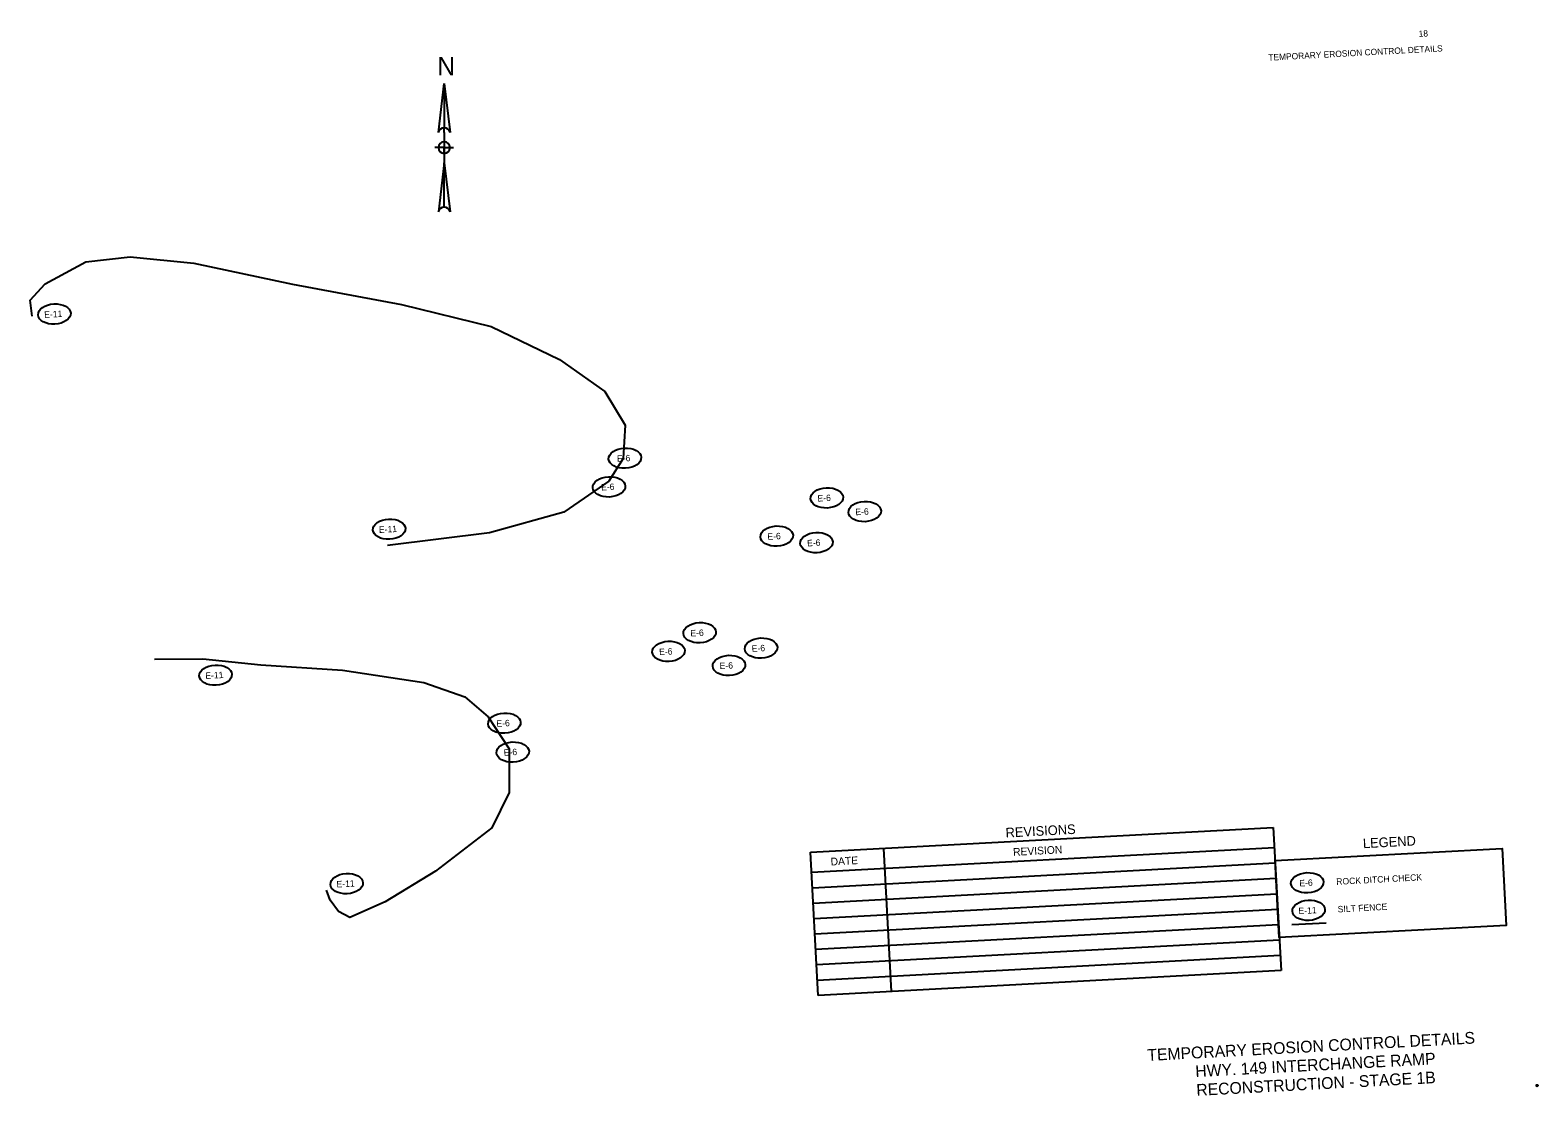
# Model space of a CAD drawing. Extents: x 251493 to 254667, y 216764 to 225410.
# Drawn here: x 251612 to 254429, y 221201 to 223192 of the extents above; entities that cross this region are included whole.
import ezdxf

# ---------------------------------------------------------------- set-up
doc = ezdxf.new("R2010")
doc.units = 0
for name, color, linetype in [('24X36', 7, 'Continuous'), ('Level 1', 7, 'Continuous'), ('Level 2', 7, 'Continuous'), ('Level 30', 7, 'Continuous')]:
    doc.layers.add(name, color=color, linetype=linetype)

msp = doc.modelspace()

# ---------------------------------------------------------------- linework, layer by layer
at = {"layer": '24X36'}
msp.add_line((253969.6, 221520.8), (254033.6, 221524.3), dxfattribs=at)
for points in [[(251615.8, 222657.8), (251611.8, 222687.5), (251640.1, 222717.7), (251715.6, 222758.8), (251798.9, 222768.1), (251917.9, 222756.5), (252101.8, 222717.3), (252306, 222679.2), (252473.2, 222638), (252600.9, 222576.6), (252685.5, 222516.6), (252723.5, 222454), (252719.7, 222391.6), (252693.2, 222349.5), (252609, 222291.2), (252470, 222252.7), (252279.8, 222229.3)], [(251843.9, 222017), (251934.8, 222017.1), (252043, 222006.1), (252195.4, 221996.3), (252347.4, 221973.4), (252424.2, 221946.4), (252468, 221909.3), (252507.1, 221849.2), (252506.7, 221767.8), (252474.4, 221701.5), (252369.3, 221620.5), (252275.4, 221563.5), (252209.4, 221534.2), (252187.9, 221545.6), (252172.4, 221566.3), (252165.4, 221585.1)]]:
    msp.add_lwpolyline(points, dxfattribs=at)
for centre in [(251657.2, 222661.5), (252723.2, 222392.2), (252693.5, 222338.6), (252282.7, 222259.6), (251958.3, 221986.9), (252498, 221897.2), (252513.7, 221843.1), (252203.4, 221597.4)]:
    msp.add_ellipse(centre, major_axis=(30.4, 1.6), ratio=0.622507, dxfattribs=at)
at = {"layer": 'Level 1'}
for p, q in [((252374.6, 223000.8), (252385.5, 223092.2)), ((252385.5, 223092.2), (252396.4, 223000.8)), ((252385.5, 223092.2), (252385.5, 223009.4)), ((252385.5, 223000.8), (252385.5, 223009.4)), ((252385.5, 223000.8), (252385.5, 222983.3)), ((252374.2, 222972.4), (252368.1, 222972.4)), ((252385.5, 222972.4), (252375, 222972.4)), ((252385.5, 222983.3), (252385.5, 222972.4)), ((252385.5, 222972.4), (252385.5, 222961.6)), ((252385.5, 222972.4), (252396.4, 222972.4)), ((252385.5, 222961.6), (252385.5, 222972.4)), ((252396.4, 222972.4), (252402.9, 222972.4)), ((252396.4, 222972.4), (252396.4, 222972.4)), ((252385.5, 222944.1), (252374.6, 222852.7)), ((252385.5, 222961.6), (252385.5, 222944.1)), ((252385.5, 222861.4), (252385.5, 222944.1)), ((252385.5, 222944.1), (252396.4, 222852.7)), ((253069.9, 221655.9), (253934.9, 221702.3)), ((253934.9, 221702.3), (253949.3, 221434.8)), ((253084.3, 221388.4), (253069.9, 221655.9)), ((253071.9, 221618.5), (253936.9, 221664.8)), ((253206.3, 221663.2), (253220.6, 221395.7)), ((253073.5, 221589.7), (253938.5, 221636.1)), ((253075, 221561), (253940, 221607.3)), ((253076.6, 221532.2), (253941.6, 221578.6)), ((253078.1, 221503.5), (253943.1, 221549.8)), ((253079.6, 221474.7), (253944.7, 221521.1)), ((253081.2, 221446), (253946.2, 221492.3)), ((253082.7, 221417.2), (253947.7, 221463.5)), ((253949.3, 221434.8), (253084.3, 221388.4)), ((253949.3, 221434.8), (253949.3, 221434.8))]:
    msp.add_line(p, q, dxfattribs=at)
msp.add_lwpolyline([(253938.3, 221640.4), (254362.4, 221663.1), (254370.1, 221519.3), (253946, 221496.6)], close=True, dxfattribs=at)
for points in [[(254427.2, 221221), (254425.9, 221220.9), (254425.9, 221220.7), (254426.4, 221220.8), (254426.5, 221219.3), (254426.7, 221219.3), (254426.7, 221220.8), (254427.2, 221220.8), (254427.2, 221221)], [(254427.7, 221220.7), (254427.7, 221220.7), (254428.3, 221219.3), (254428.4, 221219.4), (254428.9, 221220.8), (254428.9, 221220.8), (254429, 221219.4), (254429.2, 221219.4), (254429.1, 221221.1), (254428.8, 221221.1), (254428.3, 221219.6), (254427.7, 221221), (254427.4, 221221), (254427.5, 221219.3), (254427.7, 221219.3), (254427.7, 221220.7)]]:
    msp.add_lwpolyline(points, dxfattribs=at)
for centre, radius, start, end in [((252385.5, 222998.3), 11.2, 90, 167.3196), ((252385.5, 222998.3), 11.2, 12.6804, 90), ((252385.5, 222972.4), 10.9, 90, 180), ((252385.5, 222972.4), 10.9, 180, 270), ((252385.5, 222972.4), 10.9, 0, 90), ((252385.5, 222972.4), 10.9, 270, 0), ((252385.5, 222850.2), 11.2, 90, 167.3196), ((252385.5, 222850.2), 11.2, 12.6804, 90)]:
    msp.add_arc(centre, radius, start, end, dxfattribs=at)
at = {"layer": 'Level 30'}
for centre in [(253100.6, 222318), (253171.4, 222292.5), (253007, 222246.6), (253081.2, 222234.5), (252863, 222066.1), (252804.7, 222031.3), (252977.7, 222037.4), (252917.7, 222005), (253998.3, 221599), (254001, 221547.5)]:
    msp.add_ellipse(centre, major_axis=(30.4, 1.6), ratio=0.622507, dxfattribs=at)

# ---------------------------------------------------------------- texts
at = {"layer": '24X36'}
for s, p in [('E-11', (251638.4, 222654.3)), ('E-6', (252708.7, 222385.3)), ('E-6', (252679, 222331.7)), ('E-11', (252263.9, 222252.5)), ('E-11', (251939.5, 221979.7)), ('E-6', (252483.4, 221890.3)), ('E-6', (252497.1, 221836.3)), ('E-11', (252184.6, 221590.2))]:
    msp.add_text(s, height=12, rotation=3.0666, dxfattribs=at).set_placement(p)
at = {"layer": 'Level 1'}
for s, height, p in [('18', 11.72, (254206.8, 223179.2)), ('TEMPORARY EROSION CONTROL DETAILS', 11.7, (253926, 223134.8)), ('DATE', 14.4, (253108, 221631.2)), ('REVISION', 14.4, (253448.9, 221649.2))]:
    msp.add_text(s, height=height, rotation=3.0666, dxfattribs=at).set_placement(p)
msp.add_text('N', height=34.2, dxfattribs=at).set_placement((252372.9, 223107.3))
at = {"layer": 'Level 2'}
for s, p in [('TEMPORARY EROSION CONTROL DETAILS', (253700.1, 221266)), ('HWY. 149 INTERCHANGE RAMP', (253789.7, 221235.8)), ('RECONSTRUCTION - STAGE 1B', (253791.6, 221200.8))]:
    msp.add_text(s, height=22, rotation=3.0666, dxfattribs=at).set_placement(p)
at = {"layer": 'Level 30'}
for s, height, p in [('E-6', 12, (253083.4, 222311)), ('E-6', 12, (253154.2, 222285.5)), ('E-6', 12, (252989.8, 222239.6)), ('E-6', 12, (253064, 222227.4)), ('E-6', 12, (252845.8, 222059.1)), ('E-6', 12, (252787.5, 222024.2)), ('E-6', 12, (252960.5, 222030.4)), ('E-6', 12, (252900.5, 221998)), ('REVISIONS', 18, (253435, 221683.4)), ('LEGEND', 18, (254102.8, 221663.5)), ('ROCK DITCH CHECK', 11.997, (254052.8, 221595)), ('E-6', 12, (253983.8, 221592.1)), ('SILT FENCE ', 11.997, (254055.5, 221543.5)), ('E-11', 12, (253982.2, 221540.3))]:
    msp.add_text(s, height=height, rotation=3.0666, dxfattribs=at).set_placement(p)

doc.saveas('drawing.dxf')
